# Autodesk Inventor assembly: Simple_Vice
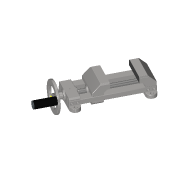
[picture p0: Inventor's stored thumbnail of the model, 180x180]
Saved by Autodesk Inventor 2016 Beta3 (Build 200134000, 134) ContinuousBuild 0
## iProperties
Created: 2016-02
Part Number: Simple_Vice
Document SubType Name: Assembly
Designer: Vertex
Mass: 10597.2 g
Surface Area: 2647.41 cm^2
Volume: 1381.25 cm^3
Density: 7.67217 g/cm^3
Author: Vertex
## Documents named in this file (9)
- D:\My Data\Books_Final Books\Autodesk Inventor 2015_resources\Chapter 7\simple-vice\Simple_Vice.iam
- D:\My Data\Books_Final Books\Autodesk Inventor 2015_resources\Chapter 7\simple-vice\Fixed Jaw.ipt
- D:\My Data\Books_Final Books\Autodesk Inventor 2015_resources\Chapter 7\simple-vice\Holder.ipt
- D:\My Data\Books_Final Books\Autodesk Inventor 2015_resources\Chapter 7\simple-vice\Movable_jaw.ipt
- D:\My Data\Books_Final Books\Autodesk Inventor 2015_resources\Chapter 7\simple-vice\Base_plate.ipt
- D:\My Data\Books_Final Books\Autodesk Inventor 2015_resources\Chapter 7\simple-vice\Screw.ipt
- D:\My Data\Books_Final Books\Autodesk Inventor 2015_resources\Chapter 7\simple-vice\Wheel.ipt
- D:\My Data\Books_Final Books\Autodesk Inventor 2015_resources\Chapter 7\simple-vice\Handle.ipt
- D:\My Data\Books_Final Books\Autodesk Inventor 2015_resources\Chapter 7\simple-vice\Washer.ipt
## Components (9 placed, 8 different names)
1. Holder:1 — Insert:14, Insert:15, Insert:16, Insert:26
2. Fixed Jaw:1 — Insert:17, Insert:18, Insert:19, Insert:20
3. Movable_jaw:1 — Mate:6, Mate:7, Mate:8, Mate:9, Cylindrical:1, Rotation/Translation:1
4. Base_plate:1 — Insert:15, Insert:16, Mate:7, Mate:9, Insert:17, Insert:18
5. Base_plate:2 — Insert:14, Mate:6, Mate:8, Insert:19, Insert:20
6. Screw:1 — Cylindrical:1, Mate:11, Mate:12, Rotation/Translation:1
7. Wheel:1 — Mate:11, Mate:12, Insert:23, Insert:24, Insert:26
8. Handle:1 — Insert:23
9. Washer:1 — Insert:24
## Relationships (18: Insert 10, Mate 6, CylindricalJoint 1, RelateRotateTranslate 1)
- Insert:14: Holder:1 ↔ Base_plate:2
- Insert:15: Holder:1 ↔ Base_plate:1
- Insert:16: Holder:1 ↔ Base_plate:1
- Mate:6: Movable_jaw:1 ↔ Base_plate:2
- Mate:7: Movable_jaw:1 ↔ Base_plate:1
- Mate:8: Movable_jaw:1 ↔ Base_plate:2
- Mate:9: Movable_jaw:1 ↔ Base_plate:1
- Insert:17: Fixed Jaw:1 ↔ Base_plate:1
- Insert:18: Fixed Jaw:1 ↔ Base_plate:1
- Insert:19: Fixed Jaw:1 ↔ Base_plate:2
- Insert:20: Fixed Jaw:1 ↔ Base_plate:2
- Cylindrical:1: Movable_jaw:1 ↔ Screw:1
- Mate:11: Screw:1 ↔ Wheel:1
- Mate:12: Screw:1 ↔ Wheel:1
- Insert:23: Wheel:1 ↔ Handle:1
- Insert:24: Wheel:1 ↔ Washer:1
- Rotation/Translation:1 [RelateRotateTranslate]: Movable_jaw:1 ↔ Screw:1
- Insert:26: Holder:1 ↔ Wheel:1
## Named parameters: sa_0 = -686305.37192 mm, sa_1 = 0 deg, sa_2 = 1333785.94102 mm, sa_3 = 686305.37192 mm, sa_4 = 0 deg, sa_5 = -1333785.94102 mm, sa_7 = 50000 mm
